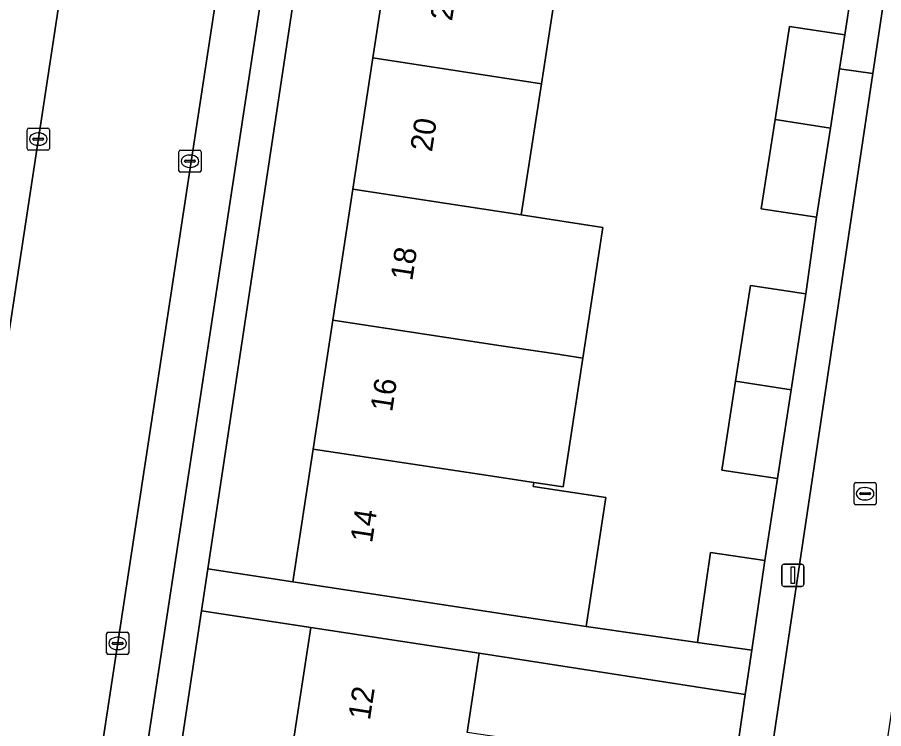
# Model space of a CAD drawing. Extents: x 161084 to 161928, y 385354 to 386522.
# Drawn here: x 161719.79 to 161758.92, y 385457.02 to 385489.13 of the extents above; entities that cross this region are included whole.
import ezdxf

# ---------------------------------------------------------------- set-up
doc = ezdxf.new("R2010")
doc.units = 0
for name, color, linetype in [('IMGEO_Erf', 7, 'Continuous'), ('IMGEO_Kolk', 7, 'Continuous'), ('IMGEO_Lichtmast', 7, 'Continuous'), ('IMGEO_Pand', 7, 'Continuous'), ('IMGEO_Pand_nummerreeks', 7, 'Continuous'), ('IMGEO_Parkeervlak_open', 7, 'Continuous'), ('IMGEO_Rijbaan_lokaal_open', 7, 'Continuous'), ('IMGEO_Voetpad_open', 7, 'Continuous')]:
    doc.layers.add(name, color=color, linetype=linetype)

msp = doc.modelspace()

# ---------------------------------------------------------------- linework, layer by layer
at = {"layer": 'IMGEO_Erf'}
for points in [[(161733.786, 385500), (161728.394, 385464.232), (161732.227, 385463.642), (161733.145, 385469.634), (161734.039, 385475.466), (161734.945, 385481.377), (161735.852, 385487.298), (161736.757, 385493.2)], [(161744.364, 385492.033), (161743.461, 385486.131), (161742.554, 385480.21), (161746.238, 385479.645), (161745.335, 385473.749), (161744.444, 385467.935), (161743.116, 385468.137), (161743.087, 385467.949), (161746.37, 385467.449), (161745.485, 385461.627), (161750.518, 385460.91), (161751.095, 385464.966), (161753.545, 385464.617), (161754.117, 385468.309), (161751.617, 385468.694), (161752.234, 385472.7), (161752.902, 385477.031), (161755.402, 385476.646), (161755.887, 385480.103), (161753.392, 385480.489), (161754.015, 385484.512), (161754.667, 385488.722), (161757.162, 385488.336), (161757.736, 385492.084)], [(161732.109, 385455.505), (161733.041, 385461.588), (161728.109, 385462.344), (161723, 385428.458)], [(161752.359, 385456.476), (161752.67, 385458.561), (161740.652, 385460.422), (161740.103, 385456.843)]]:
    msp.add_lwpolyline(points, dxfattribs=at)
at = {"layer": 'IMGEO_Kolk'}
for p, q in [((161720.237, 385483.206), (161720.237, 385484.058)), ((161720.312, 385484.132), (161721.164, 385484.132)), ((161720.725, 385483.912), (161720.75, 385483.912)), ((161721.238, 385484.058), (161721.238, 385483.206)), ((161720.496, 385483.626), (161720.496, 385483.638)), ((161720.934, 385483.589), (161720.536, 385483.589)), ((161720.539, 385483.675), (161720.937, 385483.675)), ((161720.98, 385483.638), (161720.98, 385483.626)), ((161721.164, 385483.132), (161720.312, 385483.132)), ((161720.748, 385483.352), (161720.723, 385483.352)), ((161727.087, 385482.208), (161727.087, 385483.06)), ((161727.162, 385483.134), (161728.014, 385483.134)), ((161728.088, 385483.06), (161728.088, 385482.208)), ((161727.346, 385482.628), (161727.346, 385482.64)), ((161727.389, 385482.677), (161727.787, 385482.677)), ((161727.575, 385482.914), (161727.6, 385482.914)), ((161727.83, 385482.64), (161727.83, 385482.628)), ((161727.784, 385482.591), (161727.386, 385482.591)), ((161727.598, 385482.354), (161727.573, 385482.354)), ((161728.014, 385482.134), (161727.162, 385482.134)), ((161757.58, 385467.201), (161757.58, 385468.053)), ((161757.655, 385468.127), (161758.507, 385468.127)), ((161758.068, 385467.907), (161758.093, 385467.907)), ((161758.581, 385468.053), (161758.581, 385467.201)), ((161757.839, 385467.621), (161757.839, 385467.633)), ((161758.277, 385467.584), (161757.879, 385467.584)), ((161757.882, 385467.67), (161758.28, 385467.67)), ((161758.323, 385467.633), (161758.323, 385467.621)), ((161758.507, 385467.127), (161757.655, 385467.127)), ((161758.091, 385467.347), (161758.066, 385467.347)), ((161723.822, 385460.444), (161723.822, 385461.296)), ((161723.897, 385461.37), (161724.749, 385461.37)), ((161724.31, 385461.15), (161724.335, 385461.15)), ((161724.823, 385461.296), (161724.823, 385460.444)), ((161724.081, 385460.864), (161724.081, 385460.876)), ((161724.519, 385460.827), (161724.121, 385460.827)), ((161724.124, 385460.913), (161724.522, 385460.913)), ((161724.565, 385460.876), (161724.565, 385460.864)), ((161724.749, 385460.37), (161723.897, 385460.37)), ((161724.333, 385460.59), (161724.308, 385460.59))]:
    msp.add_line(p, q, dxfattribs=at)
for points in [[(161720.237, 385483.206), (161720.237, 385484.058)], [(161720.312, 385484.132), (161721.164, 385484.132)], [(161721.238, 385484.058), (161721.238, 385483.206)], [(161721.164, 385483.132), (161720.312, 385483.132)], [(161727.087, 385482.208), (161727.087, 385483.06)], [(161727.162, 385483.134), (161728.014, 385483.134)], [(161728.088, 385483.06), (161728.088, 385482.208)], [(161728.014, 385482.134), (161727.162, 385482.134)], [(161757.58, 385467.201), (161757.58, 385468.053)], [(161757.655, 385468.127), (161758.507, 385468.127)], [(161758.581, 385468.053), (161758.581, 385467.201)], [(161758.507, 385467.127), (161757.655, 385467.127)], [(161723.822, 385460.444), (161723.822, 385461.296)], [(161723.897, 385461.37), (161724.749, 385461.37)], [(161724.823, 385461.296), (161724.823, 385460.444)], [(161724.749, 385460.37), (161723.897, 385460.37)]]:
    msp.add_lwpolyline(points, dxfattribs=at)
for centre, radius, start, end in [((161720.314, 385484.056), 0.0765, 91.552, 178.448), ((161720.314, 385484.056), 0.0765, 91.552, 178.448), ((161721.162, 385484.056), 0.0765, 1.552, 88.448), ((161721.162, 385484.056), 0.0765, 1.552, 88.448), ((161720.536, 385483.635), 0.0403, 85.8775, 175.7526), ((161720.533, 385483.625), 0.0366, 178.938, 274.7102), ((161720.937, 385483.632), 0.043, 264.8664, 352.4533), ((161720.941, 385483.637), 0.0386, 1.7309, 96.639), ((161720.314, 385483.208), 0.0765, 181.552, 268.448), ((161720.314, 385483.208), 0.0765, 181.552, 268.448), ((161721.162, 385483.208), 0.0765, 271.552, 358.448), ((161721.162, 385483.208), 0.0765, 271.552, 358.448), ((161727.164, 385483.058), 0.0765, 91.552, 178.448), ((161727.164, 385483.058), 0.0765, 91.552, 178.448), ((161728.012, 385483.058), 0.0765, 1.552, 88.448), ((161728.012, 385483.058), 0.0765, 1.552, 88.448), ((161727.386, 385482.637), 0.0403, 85.8775, 175.7526), ((161727.383, 385482.627), 0.0366, 178.938, 274.7102), ((161727.787, 385482.634), 0.043, 264.8664, 352.4533), ((161727.791, 385482.639), 0.0386, 1.7309, 96.639), ((161727.164, 385482.21), 0.0765, 181.552, 268.448), ((161727.164, 385482.21), 0.0765, 181.552, 268.448), ((161728.012, 385482.21), 0.0765, 271.552, 358.448), ((161728.012, 385482.21), 0.0765, 271.552, 358.448), ((161757.657, 385468.051), 0.0765, 91.552, 178.448), ((161757.657, 385468.051), 0.0765, 91.552, 178.448), ((161758.505, 385468.051), 0.0765, 1.552, 88.448), ((161758.505, 385468.051), 0.0765, 1.552, 88.448), ((161757.879, 385467.63), 0.0403, 85.8775, 175.7526), ((161757.876, 385467.62), 0.0366, 178.938, 274.7102), ((161758.28, 385467.627), 0.043, 264.8664, 352.4533), ((161758.284, 385467.632), 0.0386, 1.7309, 96.639), ((161757.657, 385467.203), 0.0765, 181.552, 268.448), ((161757.657, 385467.203), 0.0765, 181.552, 268.448), ((161758.505, 385467.203), 0.0765, 271.552, 358.448), ((161758.505, 385467.203), 0.0765, 271.552, 358.448), ((161723.899, 385461.294), 0.0765, 91.552, 178.448), ((161723.899, 385461.294), 0.0765, 91.552, 178.448), ((161724.747, 385461.294), 0.0765, 1.552, 88.448), ((161724.747, 385461.294), 0.0765, 1.552, 88.448), ((161724.121, 385460.873), 0.0403, 85.8775, 175.7526), ((161724.118, 385460.863), 0.0366, 178.938, 274.7102), ((161724.522, 385460.87), 0.043, 264.8664, 352.4533), ((161724.526, 385460.875), 0.0386, 1.7309, 96.639), ((161723.899, 385460.446), 0.0765, 181.552, 268.448), ((161723.899, 385460.446), 0.0765, 181.552, 268.448), ((161724.747, 385460.446), 0.0765, 271.552, 358.448), ((161724.747, 385460.446), 0.0765, 271.552, 358.448)]:
    msp.add_arc(centre, radius, start, end, dxfattribs=at)
for centre, major_axis, ratio, start_param, end_param in [((161720.724, 385483.632), (-0.387, 0.002), 0.722429, 4.712389, 7.853982), ((161720.749, 385483.632), (-0.39, 0.002), 0.717154, 1.570796, 4.712389), ((161727.574, 385482.634), (-0.387, 0.002), 0.722429, 4.712389, 7.853982), ((161727.599, 385482.634), (-0.39, 0.002), 0.717154, 1.570796, 4.712389), ((161758.067, 385467.627), (-0.387, 0.002), 0.722429, 4.712389, 7.853982), ((161758.092, 385467.627), (-0.39, 0.002), 0.717154, 1.570796, 4.712389), ((161724.309, 385460.87), (-0.387, 0.002), 0.722429, 4.712389, 7.853982), ((161724.334, 385460.87), (-0.39, 0.002), 0.717154, 1.570796, 4.712389)]:
    msp.add_ellipse(centre, major_axis=major_axis, ratio=ratio, start_param=start_param, end_param=end_param, dxfattribs=at)
at = {"layer": 'IMGEO_Lichtmast'}
for p, q in [((161754.316, 385463.544), (161754.316, 385464.344)), ((161754.316, 385464.344), (161754.316, 385463.544)), ((161754.416, 385464.444), (161755.206, 385464.444)), ((161755.206, 385464.444), (161754.416, 385464.444)), ((161755.306, 385464.344), (161755.306, 385463.544)), ((161755.306, 385463.544), (161755.306, 385464.344)), ((161755.206, 385463.444), (161754.416, 385463.444)), ((161754.416, 385463.444), (161755.206, 385463.444))]:
    msp.add_line(p, q, dxfattribs=at)
msp.add_lwpolyline([(161754.736, 385464.319), (161754.886, 385464.319), (161754.886, 385463.569), (161754.736, 385463.569), (161754.736, 385464.319)], dxfattribs=at)
for centre, start, end in [((161754.416, 385464.344), 90, 180), ((161754.416, 385464.344), 90, 180), ((161755.206, 385464.344), 0, 90), ((161755.206, 385464.344), 360, 90), ((161754.416, 385463.544), 180, 270), ((161754.416, 385463.544), 180, 270), ((161755.206, 385463.544), 270, 0), ((161755.206, 385463.544), 270, 0)]:
    msp.add_arc(centre, 0.1, start, end, dxfattribs=at)
at = {"layer": 'IMGEO_Pand'}
for points in [[(161736.757, 385493.2), (161735.852, 385487.298), (161743.461, 385486.131), (161744.364, 385492.033)], [(161756.925, 385486.803), (161757.162, 385488.336), (161754.667, 385488.722), (161754.015, 385484.512), (161756.511, 385484.13)], [(161742.554, 385480.21), (161743.461, 385486.131), (161735.852, 385487.298), (161734.945, 385481.377)], [(161756.511, 385484.13), (161754.015, 385484.512), (161753.392, 385480.489), (161755.887, 385480.103)], [(161746.238, 385479.645), (161742.554, 385480.21), (161734.945, 385481.377), (161734.039, 385475.466), (161741.65, 385474.309), (161744, 385473.952), (161745.335, 385473.749)], [(161755.402, 385476.646), (161752.902, 385477.031), (161752.234, 385472.7), (161754.735, 385472.32)], [(161745.335, 385473.749), (161744, 385473.952), (161741.65, 385474.309), (161734.039, 385475.466), (161733.145, 385469.634), (161740.76, 385468.495), (161743.116, 385468.137), (161744.444, 385467.935)], [(161754.735, 385472.32), (161752.234, 385472.7), (161751.617, 385468.694), (161754.117, 385468.309)], [(161746.37, 385467.449), (161743.087, 385467.949), (161743.116, 385468.137), (161740.76, 385468.495), (161733.145, 385469.634), (161732.227, 385463.642), (161737.171, 385462.891), (161739.84, 385462.485), (161742.202, 385462.126), (161745.485, 385461.627)], [(161753.545, 385464.617), (161751.095, 385464.966), (161750.518, 385460.91), (161752.968, 385460.561)], [(161740.652, 385460.422), (161737.984, 385460.831), (161733.041, 385461.588), (161732.109, 385455.505), (161739.726, 385454.389), (161742.417, 385453.995), (161742.777, 385456.451), (161740.103, 385456.843)]]:
    msp.add_lwpolyline(points, close=True, dxfattribs=at)
at = {"layer": 'IMGEO_Parkeervlak_open'}
msp.add_lwpolyline([(161730.285, 385500), (161720.36, 385434.843), (161720.413, 385434.972), (161720.522, 385435.194), (161720.65, 385435.404), (161720.797, 385435.603), (161720.961, 385435.787), (161721.14, 385435.956), (161721.334, 385436.109), (161721.541, 385436.243), (161721.72, 385436.327), (161721.891, 385436.427), (161722.053, 385436.542), (161722.203, 385436.671), (161722.342, 385436.813), (161722.467, 385436.967), (161722.578, 385437.131), (161722.674, 385437.304), (161722.754, 385437.486), (161722.817, 385437.673), (161722.864, 385437.866), (161722.892, 385438.055), (161732.326, 385500)], dxfattribs=at)
at = {"layer": 'IMGEO_Rijbaan_lokaal_open'}
for points in [[(161749.647, 385612.852), (161748.381, 385604.68), (161742.027, 385563.68), (161739.541, 385547.634), (161739.451, 385547.152), (161739.259, 385546.423), (161739.002, 385545.714), (161738.683, 385545.03), (161738.304, 385544.378), (161737.868, 385543.762), (161737.379, 385543.188), (161731.192, 385536.55), (161730.397, 385535.617), (161729.689, 385534.617), (161729.073, 385533.557), (161728.554, 385532.447), (161728.136, 385531.295), (161727.823, 385530.11), (161727.669, 385529.274), (161723.237, 385500), (161713.061, 385433.189)], [(161719.723, 385430.887), (161719.914, 385431.913), (161720.36, 385434.843), (161730.285, 385500), (161733.96, 385523.829), (161734.945, 385529.848), (161735.034, 385530.378), (161735.175, 385530.918), (161735.362, 385531.442), (161735.597, 385531.948), (161735.875, 385532.431), (161736.195, 385532.887), (161736.555, 385533.313), (161736.762, 385533.508), (161746.133, 385543.607), (161752.959, 385588.197)], [(161759.892, 385496.328), (161758.437, 385486.593), (161751.237, 385438.41), (161753.507, 385437.739), (161755.263, 385442.374), (161755.379, 385442.679), (161757.135, 385447.315), (161758.095, 385449.94), (161758.51, 385452.633), (161759.257, 385457.614), (161759.593, 385459.855), (161760.266, 385464.337), (161760.972, 385469.044), (161761.748, 385474.214), (161762.426, 385478.735), (161762.634, 385480.119), (161763.167, 385483.708), (161763.666, 385487.075), (161763.867, 385488.39), (161764.587, 385493.113)]]:
    msp.add_lwpolyline(points, dxfattribs=at)
at = {"layer": 'IMGEO_Voetpad_open'}
for points in [[(161699.341, 385410.516), (161709.663, 385426.482), (161711.688, 385429.614), (161712.19, 385430.579), (161712.605, 385431.585), (161712.927, 385432.624), (161713.061, 385433.189), (161723.237, 385500), (161727.669, 385529.274), (161727.823, 385530.11), (161731.045, 385551.389), (161732.828, 385563.446)], [(161717.947, 385420.67), (161720.617, 385424.785), (161721.213, 385425.704), (161723, 385428.458), (161728.109, 385462.344), (161728.394, 385464.232), (161733.786, 385500)], [(161732.326, 385500), (161722.892, 385438.055), (161722.864, 385437.866), (161722.817, 385437.673), (161722.754, 385437.486), (161722.674, 385437.304), (161722.578, 385437.131), (161722.467, 385436.967), (161722.342, 385436.813), (161722.203, 385436.671), (161722.053, 385436.542), (161721.891, 385436.427), (161721.72, 385436.327), (161721.541, 385436.243), (161721.334, 385436.109), (161721.14, 385435.956), (161720.961, 385435.787), (161720.797, 385435.603), (161720.65, 385435.404), (161720.522, 385435.194), (161720.413, 385434.972), (161720.36, 385434.843), (161719.914, 385431.913), (161719.723, 385430.887)], [(161751.237, 385438.41), (161758.437, 385486.593), (161756.925, 385486.803), (161756.511, 385484.13), (161755.887, 385480.103), (161755.402, 385476.646), (161754.735, 385472.32), (161754.117, 385468.309), (161753.545, 385464.617), (161752.968, 385460.561), (161752.67, 385458.561), (161752.359, 385456.476)]]:
    msp.add_lwpolyline(points, dxfattribs=at)
for points in [[(161757.736, 385492.084), (161757.162, 385488.336), (161756.925, 385486.803), (161758.437, 385486.593), (161759.892, 385496.328), (161758.382, 385496.552), (161758.296, 385495.956)], [(161745.485, 385461.627), (161742.202, 385462.126), (161739.84, 385462.485), (161737.171, 385462.891), (161732.227, 385463.642), (161728.394, 385464.232), (161728.109, 385462.344), (161733.041, 385461.588), (161737.984, 385460.831), (161740.652, 385460.422), (161752.67, 385458.561), (161752.968, 385460.561), (161750.518, 385460.91)]]:
    msp.add_lwpolyline(points, close=True, dxfattribs=at)

# ---------------------------------------------------------------- texts
at = {"layer": 'IMGEO_Pand_nummerreeks'}
for s, rotation, p in [('22', 81.287, (161739.421, 385488.934)), ('20', 81.287, (161738.516, 385483.027)), ('18', 81.2855, (161737.624, 385477.205)), ('16', 81.2855, (161736.717, 385471.288)), ('14', 81.2855, (161735.811, 385465.375)), ('12', 81.2913, (161735.714, 385457.374))]:
    msp.add_text(s, height=1, rotation=rotation, dxfattribs=at).set_placement(p)

doc.saveas('drawing.dxf')
